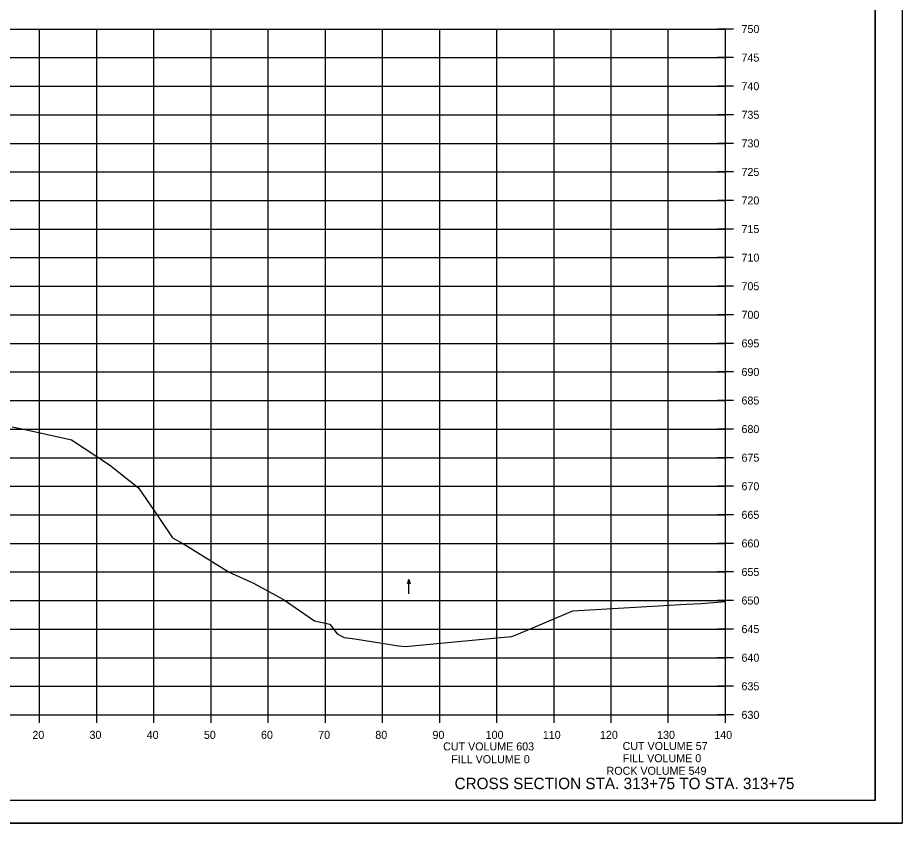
# Model space of a CAD drawing. Extents: x 1370515 to 1370849, y 383299 to 386073.
# Drawn here: x 1370694 to 1370848.7, y 385859.5 to 386000.4 of the extents above; entities that cross this region are included whole.
import ezdxf

# ---------------------------------------------------------------- set-up
doc = ezdxf.new("R2010")
doc.units = 0
for name, color, linetype in [('R_Axis', 7, 'Continuous'), ('R_Axis Annot', 7, 'Continuous'), ('R_Border', 7, 'Continuous'), ('R_Draft', 7, 'Continuous'), ('R_Exist Surface', 7, 'Continuous'), ('R_Grid', 7, 'Continuous'), ('R_No Plot', 7, 'Continuous'), ('R_Water Annot', 7, 'Continuous')]:
    doc.layers.add(name, color=color, linetype=linetype)

msp = doc.modelspace()

# ---------------------------------------------------------------- linework, layer by layer
at = {"layer": 'R_Axis'}
for p, q in [((1370819.2, 385998.46), (1370816.4, 385998.46)), ((1370817.8, 385878.46), (1370817.8, 385998.46)), ((1370819.2, 385993.46), (1370816.4, 385993.46)), ((1370819.2, 385988.46), (1370816.4, 385988.46)), ((1370819.2, 385983.46), (1370816.4, 385983.46)), ((1370819.2, 385978.46), (1370816.4, 385978.46)), ((1370819.2, 385973.46), (1370816.4, 385973.46)), ((1370819.2, 385968.46), (1370816.4, 385968.46)), ((1370819.2, 385963.46), (1370816.4, 385963.46)), ((1370819.2, 385958.46), (1370816.4, 385958.46)), ((1370819.2, 385953.46), (1370816.4, 385953.46)), ((1370819.2, 385948.46), (1370816.4, 385948.46)), ((1370819.2, 385943.46), (1370816.4, 385943.46)), ((1370819.2, 385938.46), (1370816.4, 385938.46)), ((1370819.2, 385933.46), (1370816.4, 385933.46)), ((1370819.2, 385928.46), (1370816.4, 385928.46)), ((1370819.2, 385923.46), (1370816.4, 385923.46)), ((1370819.2, 385918.46), (1370816.4, 385918.46)), ((1370819.2, 385913.46), (1370816.4, 385913.46)), ((1370819.2, 385908.46), (1370816.4, 385908.46)), ((1370819.2, 385903.46), (1370816.4, 385903.46)), ((1370819.2, 385898.46), (1370816.4, 385898.46)), ((1370819.2, 385893.46), (1370816.4, 385893.46)), ((1370819.2, 385888.46), (1370816.4, 385888.46)), ((1370819.2, 385883.46), (1370816.4, 385883.46)), ((1370697.8, 385877.06), (1370697.8, 385879.86)), ((1370707.8, 385877.06), (1370707.8, 385879.86)), ((1370717.8, 385877.06), (1370717.8, 385879.86)), ((1370727.8, 385877.06), (1370727.8, 385879.86)), ((1370737.8, 385877.06), (1370737.8, 385879.86)), ((1370747.8, 385877.06), (1370747.8, 385879.86)), ((1370757.8, 385877.06), (1370757.8, 385879.86)), ((1370767.8, 385877.06), (1370767.8, 385879.86)), ((1370777.8, 385877.06), (1370777.8, 385879.86)), ((1370787.8, 385877.06), (1370787.8, 385879.86)), ((1370797.8, 385877.06), (1370797.8, 385879.86)), ((1370807.8, 385877.06), (1370807.8, 385879.86)), ((1370817.8, 385877.06), (1370817.8, 385879.86)), ((1370537.8, 385878.46), (1370817.8, 385878.46)), ((1370819.2, 385878.46), (1370816.4, 385878.46))]:
    msp.add_line(p, q, dxfattribs=at)
at = {"layer": 'R_Border'}
for q in [(1370843.98, 386068.92), (1370527.8, 385863.46)]:
    msp.add_line((1370843.98, 385863.46), q, dxfattribs=at)
at = {"layer": 'R_Exist Surface'}
msp.add_lwpolyline([(1370692.99, 385928.85), (1370695.8, 385928.27), (1370703.36, 385926.56), (1370710.06, 385922.18), (1370715.08, 385918.16), (1370718.67, 385912.99), (1370721.08, 385909.45), (1370722.99, 385908.36), (1370730.98, 385903.4), (1370735.08, 385901.54), (1370740.47, 385898.64), (1370745.92, 385894.9), (1370748.59, 385894.32), (1370749.89, 385892.62), (1370751.06, 385891.98), (1370752.93, 385891.74), (1370760.57, 385890.56), (1370761.78, 385890.43), (1370778.44, 385891.97), (1370780.41, 385892.18), (1370781.58, 385892.63), (1370791.07, 385896.66), (1370810.95, 385897.81), (1370813.53, 385897.95), (1370814.32, 385897.99), (1370815.01, 385898.08), (1370817.8, 385898.27)], dxfattribs=at)
at = {"layer": 'R_Grid'}
for p, q in [((1370537.8, 385998.46), (1370817.8, 385998.46)), ((1370697.8, 385878.46), (1370697.8, 385998.46)), ((1370707.8, 385878.46), (1370707.8, 385998.46)), ((1370717.8, 385878.46), (1370717.8, 385998.46)), ((1370727.8, 385878.46), (1370727.8, 385998.46)), ((1370737.8, 385878.46), (1370737.8, 385998.46)), ((1370747.8, 385878.46), (1370747.8, 385998.46)), ((1370757.8, 385878.46), (1370757.8, 385998.46)), ((1370767.8, 385878.46), (1370767.8, 385998.46)), ((1370777.8, 385878.46), (1370777.8, 385998.46)), ((1370787.8, 385878.46), (1370787.8, 385998.46)), ((1370797.8, 385878.46), (1370797.8, 385998.46)), ((1370807.8, 385878.46), (1370807.8, 385998.46)), ((1370817.8, 385878.46), (1370817.8, 385998.46)), ((1370537.8, 385993.46), (1370817.8, 385993.46)), ((1370537.8, 385988.46), (1370817.8, 385988.46)), ((1370537.8, 385983.46), (1370817.8, 385983.46)), ((1370537.8, 385978.46), (1370817.8, 385978.46)), ((1370537.8, 385973.46), (1370817.8, 385973.46)), ((1370537.8, 385968.46), (1370817.8, 385968.46)), ((1370537.8, 385963.46), (1370817.8, 385963.46)), ((1370537.8, 385958.46), (1370817.8, 385958.46)), ((1370537.8, 385953.46), (1370817.8, 385953.46)), ((1370537.8, 385948.46), (1370817.8, 385948.46)), ((1370537.8, 385943.46), (1370817.8, 385943.46)), ((1370537.8, 385938.46), (1370817.8, 385938.46)), ((1370537.8, 385933.46), (1370817.8, 385933.46)), ((1370537.8, 385928.46), (1370817.8, 385928.46)), ((1370537.8, 385923.46), (1370817.8, 385923.46)), ((1370537.8, 385918.46), (1370817.8, 385918.46)), ((1370537.8, 385913.46), (1370817.8, 385913.46)), ((1370537.8, 385908.46), (1370817.8, 385908.46)), ((1370537.8, 385903.46), (1370817.8, 385903.46)), ((1370537.8, 385898.46), (1370817.8, 385898.46)), ((1370537.8, 385893.46), (1370817.8, 385893.46)), ((1370537.8, 385888.46), (1370817.8, 385888.46)), ((1370537.8, 385883.46), (1370817.8, 385883.46)), ((1370537.8, 385878.46), (1370817.8, 385878.46))]:
    msp.add_line(p, q, dxfattribs=at)
at = {"layer": 'R_No Plot'}
msp.add_line((1370515.4, 385859.49), (1370848.73, 385859.49), dxfattribs=at)
for points in [[(1370515.39, 386072.82), (1370848.73, 386072.82), (1370848.73, 385859.48), (1370515.39, 385859.48)], [(1370761.72, 386068.92), (1370761.72, 386059.04), (1370797.45, 386059.04), (1370797.45, 386056.12), (1370820.65, 386056.12), (1370820.65, 386032.91), (1370843.98, 386032.91), (1370843.98, 385863.46), (1370527.8, 385863.46), (1370527.8, 386068.92)]]:
    msp.add_lwpolyline(points, close=True, dxfattribs=at)
at = {"layer": 'R_Water Annot'}
for p, q in [((1370762.38, 385902.17), (1370762.1, 385901.41)), ((1370762.38, 385899.66), (1370762.38, 385902.17)), ((1370762.38, 385902.17), (1370762.66, 385901.41))]:
    msp.add_line(p, q, dxfattribs=at)

# ---------------------------------------------------------------- texts
at = {"layer": 'R_Axis Annot'}
for s, p in [('750', (1370820.6, 385997.76)), ('745', (1370820.6, 385992.76)), ('740', (1370820.6, 385987.76)), ('735', (1370820.6, 385982.76)), ('730', (1370820.6, 385977.76)), ('725', (1370820.6, 385972.76)), ('720', (1370820.6, 385967.76)), ('715', (1370820.6, 385962.76)), ('710', (1370820.6, 385957.76)), ('705', (1370820.6, 385952.76)), ('700', (1370820.6, 385947.76)), ('695', (1370820.6, 385942.76)), ('690', (1370820.6, 385937.76)), ('685', (1370820.6, 385932.76)), ('680', (1370820.6, 385927.76)), ('675', (1370820.6, 385922.76)), ('670', (1370820.6, 385917.76)), ('665', (1370820.6, 385912.76)), ('660', (1370820.6, 385907.76)), ('655', (1370820.6, 385902.76)), ('650', (1370820.6, 385897.76)), ('645', (1370820.6, 385892.76)), ('640', (1370820.6, 385887.76)), ('635', (1370820.6, 385882.76)), ('630', (1370820.6, 385877.76)), ('20', (1370696.54, 385874.26)), ('30', (1370706.54, 385874.26)), ('40', (1370716.54, 385874.26)), ('50', (1370726.54, 385874.26)), ('60', (1370736.54, 385874.26)), ('70', (1370746.54, 385874.26)), ('80', (1370756.54, 385874.26)), ('90', (1370766.54, 385874.26)), ('100', (1370775.84, 385874.26)), ('110', (1370785.84, 385874.26)), ('120', (1370795.84, 385874.26)), ('130', (1370805.84, 385874.26)), ('140', (1370815.84, 385874.26)), ('CUT VOLUME 603', (1370768.4, 385872.24)), ('CUT VOLUME 57', (1370799.8, 385872.31)), ('FILL VOLUME 0', (1370769.82, 385870)), ('FILL VOLUME 0', (1370799.82, 385870.17)), ('ROCK VOLUME 549', (1370796.99, 385867.97))]:
    msp.add_text(s, height=1.4, dxfattribs=at).set_placement(p)
at = {"layer": 'R_Draft'}
msp.add_text('CROSS SECTION STA. 313+75 TO STA. 313+75', height=2, dxfattribs=at).set_placement((1370770.4, 385865.46))
at = {"layer": 'R_No Plot'}
for p in [(1370703.32, 385926.51), (1370715.04, 385918.11), (1370721.04, 385909.4), (1370730.94, 385903.35), (1370740.43, 385898.59), (1370791.03, 385896.61), (1370814.28, 385897.94), (1370748.55, 385894.27), (1370780.37, 385892.13), (1370751.02, 385891.93), (1370761.73, 385890.38)]:
    msp.add_text('+', height=0.1, dxfattribs=at).set_placement(p)

doc.saveas('drawing.dxf')
